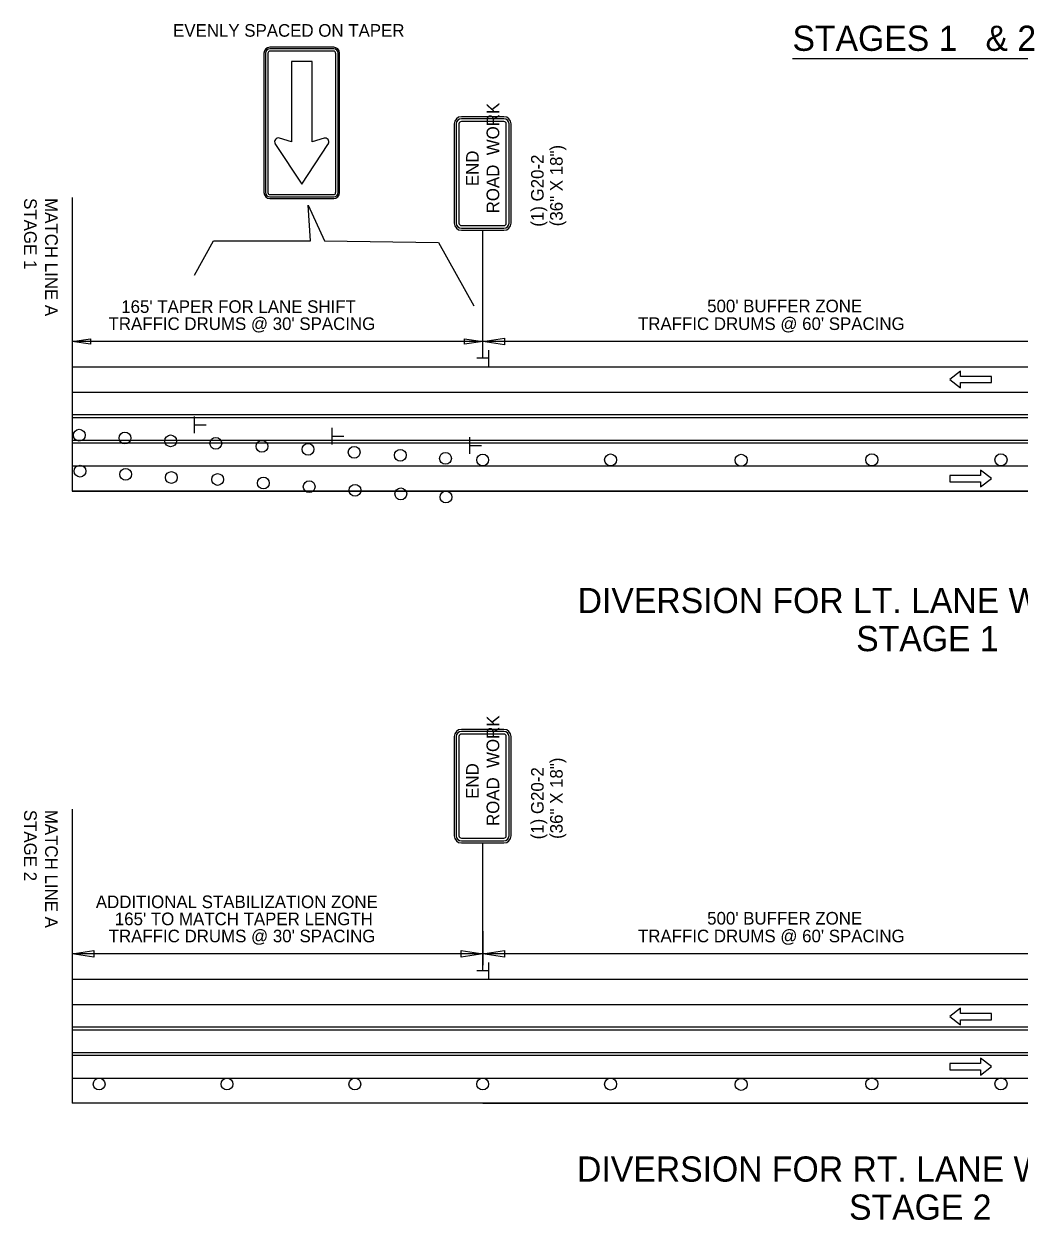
# Model space of a CAD drawing. Extents: x 1930579 to 1937984, y 596452 to 597630.
# Drawn here: x 1936470 to 1936944, y 596628 to 597198 of the extents above; entities that cross this region are included whole.
import ezdxf

# ---------------------------------------------------------------- set-up
doc = ezdxf.new("R2010")
doc.units = 0
for name, color, linetype in [('Default', 7, 'Continuous'), ('P_TC_Signs_Permanent', 7, 'Continuous'), ('P_TC_Signs_Temporary', 7, 'Continuous'), ('R_Annotation', 7, 'Continuous'), ('R_Striping', 7, 'Continuous')]:
    doc.layers.add(name, color=color, linetype=linetype)

msp = doc.modelspace()

# ---------------------------------------------------------------- linework, layer by layer
at = {"layer": 'Default'}
for p, q in [((1936835.84, 597181.22), (1936964.15, 597181.22)), ((1936493.11, 597114.97), (1936493.11, 596975.31)), ((1936493.11, 597046.45), (1936501.81, 597047.75)), ((1936688.44, 597046.45), (1936493.11, 597046.45)), ((1936501.81, 597045.15), (1936493.11, 597046.45)), ((1936501.81, 597047.75), (1936501.81, 597045.15)), ((1936679.75, 597045.15), (1936679.75, 597047.75)), ((1936679.75, 597047.75), (1936688.44, 597046.45)), ((1936688.44, 597046.45), (1936679.75, 597045.15)), ((1936997.05, 597046.45), (1936688.44, 597046.45)), ((1936688.53, 597046.45), (1936698.83, 597048)), ((1936698.83, 597044.9), (1936688.53, 597046.45)), ((1936698.83, 597048), (1936698.83, 597044.9)), ((1936691.23, 597042.43), (1936691.23, 597034.45)), ((1937498.74, 597034.31), (1936493.11, 597034.31)), ((1936691.12, 597038.47), (1936685.67, 597038.47)), ((1936493.11, 597022.31), (1937498.74, 597022.31)), ((1937498.74, 597011.52), (1936493.11, 597011.52)), ((1937498.74, 597010.14), (1936493.11, 597010.14)), ((1936551.31, 597002.87), (1936551.31, 597010.85)), ((1936551.43, 597006.84), (1936556.87, 597006.84)), ((1936616.72, 596997.46), (1936616.72, 597005.44)), ((1936616.84, 597001.42), (1936622.29, 597001.42)), ((1936682.29, 596992.94), (1936682.29, 597000.92)), ((1937498.74, 596999.41), (1936493.11, 596999.41)), ((1937498.74, 596998.03), (1936493.11, 596998.03)), ((1936682.4, 596996.91), (1936687.85, 596996.91)), ((1936493.11, 596987.31), (1937498.74, 596987.31)), ((1936493.11, 596975.31), (1936773.63, 596975.31)), ((1937498.74, 596975.31), (1936493.11, 596975.31)), ((1936757.75, 596975.31), (1937032.82, 596975.31)), ((1936493.11, 596823.85), (1936493.11, 596683.94)), ((1936688.44, 596765.87), (1936688.44, 596749.76)), ((1936493.11, 596755.08), (1936503.42, 596756.63)), ((1936503.42, 596756.63), (1936503.42, 596753.53)), ((1936678.23, 596753.53), (1936678.23, 596756.63)), ((1936678.23, 596756.63), (1936688.53, 596755.08)), ((1936688.53, 596755.08), (1936698.83, 596756.63)), ((1936698.83, 596756.63), (1936698.83, 596753.53)), ((1936688.53, 596755.08), (1936493.11, 596755.08)), ((1936503.42, 596753.53), (1936493.11, 596755.08)), ((1936688.53, 596755.08), (1936678.23, 596753.53)), ((1936997.05, 596755.08), (1936688.44, 596755.08)), ((1936698.83, 596753.53), (1936688.53, 596755.08)), ((1936691.23, 596750.89), (1936691.23, 596742.91)), ((1936691.12, 596746.92), (1936685.67, 596746.92)), ((1937498.74, 596742.94), (1936493.11, 596742.94)), ((1936493.11, 596730.94), (1937498.74, 596730.94)), ((1937498.74, 596720.15), (1936493.11, 596720.15)), ((1937498.74, 596718.77), (1936493.11, 596718.77)), ((1937498.74, 596708.04), (1936493.11, 596708.04)), ((1937498.74, 596706.66), (1936493.11, 596706.66)), ((1936493.11, 596695.94), (1937498.74, 596695.94)), ((1937498.74, 596683.94), (1936493.11, 596683.94)), ((1936688.44, 596683.94), (1936773.63, 596683.94)), ((1936757.75, 596683.94), (1937032.82, 596683.94))]:
    msp.add_line(p, q, dxfattribs=at)
for centre, radius in [((1936496.43, 597001.89), 2.81), ((1936518.18, 597000.54), 2.81), ((1936539.92, 596999.19), 2.81), ((1936561.41, 596998), 2.81), ((1936583.36, 596996.58), 2.81), ((1936605.32, 596995.17), 2.81), ((1936627.27, 596993.75), 2.81), ((1936649.22, 596992.34), 2.81), ((1936670.72, 596990.86), 2.81), ((1936688.44, 596990.1), 2.81), ((1936749.3, 596990.1), 2.87), ((1936811.44, 596989.95), 2.87), ((1936873.58, 596990.16), 2.87), ((1936935.06, 596990.17), 2.87), ((1936496.8, 596984.78), 2.81), ((1936518.53, 596983.27), 2.81), ((1936540.25, 596981.76), 2.81), ((1936562.28, 596980.82), 2.81), ((1936584.07, 596979.1), 2.81), ((1936605.86, 596977.39), 2.81), ((1936627.65, 596975.67), 2.81), ((1936649.45, 596973.95), 2.81), ((1936670.92, 596972.45), 2.81), ((1936505.88, 596693.1), 2.81), ((1936566.73, 596693.1), 2.81), ((1936627.59, 596693.1), 2.81), ((1936688.44, 596693.1), 2.81), ((1936749.3, 596693.1), 2.87), ((1936811.44, 596692.96), 2.87), ((1936873.58, 596693.16), 2.87), ((1936935.06, 596693.18), 2.87)]:
    msp.add_circle(centre, radius, dxfattribs=at)
at = {"layer": 'P_TC_Signs_Permanent'}
for p, q in [((1936584.33, 597183.71), (1936584.33, 597117.33)), ((1936585.08, 597183.71), (1936585.08, 597117.33)), ((1936586.2, 597183.71), (1936586.2, 597117.33)), ((1936617.51, 597186.52), (1936587.14, 597186.52)), ((1936617.51, 597185.77), (1936587.14, 597185.77)), ((1936617.51, 597184.65), (1936587.14, 597184.65)), ((1936618.45, 597117.33), (1936618.45, 597183.71)), ((1936619.58, 597117.33), (1936619.58, 597183.71)), ((1936620.33, 597117.33), (1936620.33, 597183.71)), ((1936587.14, 597116.4), (1936617.51, 597116.4)), ((1936587.14, 597115.27), (1936617.51, 597115.27)), ((1936587.14, 597114.52), (1936617.51, 597114.52))]:
    msp.add_line(p, q, dxfattribs=at)
for points in [[(1936612.96, 597143.22), (1936607.2, 597141.5), (1936607.2, 597179.77), (1936597.45, 597179.77), (1936597.45, 597141.5), (1936591.7, 597143.26)], [(1936589.88, 597140.26), (1936602.33, 597121.27), (1936614.73, 597140.27)]]:
    msp.add_lwpolyline(points, dxfattribs=at)
for centre, radius, start, end in [((1936587.14, 597183.71), 2.81, 90, 180), ((1936587.14, 597183.71), 2.06, 90, 180), ((1936587.14, 597183.71), 0.938, 90, 180), ((1936617.51, 597183.71), 2.81, 360, 90), ((1936617.51, 597183.71), 2.06, 360, 90), ((1936617.51, 597183.71), 0.937, 360, 90), ((1936591.21, 597141.53), 1.8, 74.0309, 213.4755), ((1936613.44, 597141.53), 1.76, 326.5994, 105.9691), ((1936527.15, 597099.16), 75, 33.2286, 33.4755), ((1936677.53, 597099.27), 75, 146.5994, 146.857), ((1936587.14, 597117.33), 2.81, 180, 270), ((1936587.14, 597117.33), 2.06, 180, 270), ((1936587.14, 597117.33), 0.938, 180, 270), ((1936617.51, 597117.33), 2.81, 270, 360), ((1936617.51, 597117.33), 2.06, 270, 360), ((1936617.51, 597117.33), 0.938, 270, 360)]:
    msp.add_arc(centre, radius, start, end, dxfattribs=at)
at = {"layer": 'P_TC_Signs_Temporary'}
for p, q in [((1936674.89, 597150.04), (1936674.89, 597102.79)), ((1936675.83, 597150.04), (1936675.83, 597102.79)), ((1936677.14, 597150.04), (1936677.14, 597102.79)), ((1936698.52, 597153.42), (1936678.27, 597153.42)), ((1936698.52, 597152.48), (1936678.27, 597152.48)), ((1936698.52, 597151.17), (1936678.27, 597151.17)), ((1936699.64, 597102.79), (1936699.64, 597150.04)), ((1936700.96, 597102.79), (1936700.96, 597150.04)), ((1936701.89, 597102.79), (1936701.89, 597150.04)), ((1936678.27, 597101.67), (1936698.52, 597101.67)), ((1936678.27, 597100.36), (1936698.52, 597100.36)), ((1936678.27, 597099.42), (1936698.52, 597099.42)), ((1936674.89, 596858.5), (1936674.89, 596811.25)), ((1936675.83, 596858.5), (1936675.83, 596811.25)), ((1936677.14, 596858.5), (1936677.14, 596811.25)), ((1936698.52, 596861.87), (1936678.27, 596861.87)), ((1936698.52, 596860.93), (1936678.27, 596860.93)), ((1936698.52, 596859.62), (1936678.27, 596859.62)), ((1936699.64, 596811.25), (1936699.64, 596858.5)), ((1936700.96, 596811.25), (1936700.96, 596858.5)), ((1936701.89, 596811.25), (1936701.89, 596858.5)), ((1936678.27, 596810.12), (1936698.52, 596810.12)), ((1936678.27, 596808.81), (1936698.52, 596808.81)), ((1936678.27, 596807.87), (1936698.52, 596807.87))]:
    msp.add_line(p, q, dxfattribs=at)
for centre, radius, start, end in [((1936678.27, 597150.04), 3.38, 90, 180), ((1936678.27, 597150.04), 2.44, 90, 180), ((1936678.27, 597150.04), 1.13, 90, 180), ((1936698.52, 597150.04), 3.38, 360, 90), ((1936698.52, 597150.04), 2.44, 360, 90), ((1936698.52, 597150.04), 1.13, 360, 90), ((1936678.27, 597102.79), 3.38, 180, 270), ((1936678.27, 597102.79), 2.44, 180, 270), ((1936678.27, 597102.79), 1.13, 180, 270), ((1936698.52, 597102.79), 2.44, 270, 360), ((1936698.52, 597102.79), 1.13, 270, 360), ((1936698.52, 597102.79), 3.38, 270, 360), ((1936678.27, 596858.5), 3.38, 90, 180), ((1936678.27, 596858.5), 2.44, 90, 180), ((1936678.27, 596858.5), 1.13, 90, 180), ((1936698.52, 596858.5), 3.38, 360, 90), ((1936698.52, 596858.5), 2.44, 360, 90), ((1936698.52, 596858.5), 1.13, 360, 90), ((1936678.27, 596811.25), 3.38, 180, 270), ((1936678.27, 596811.25), 2.44, 180, 270), ((1936678.27, 596811.25), 1.13, 180, 270), ((1936698.52, 596811.25), 2.44, 270, 360), ((1936698.52, 596811.25), 1.13, 270, 360), ((1936698.52, 596811.25), 3.38, 270, 360)]:
    msp.add_arc(centre, radius, start, end, dxfattribs=at)
at = {"layer": 'R_Annotation'}
for p, q in [((1936688.39, 597099.42), (1936688.39, 597038.47)), ((1936688.39, 596807.87), (1936688.39, 596746.92))]:
    msp.add_line(p, q, dxfattribs=at)
msp.add_lwpolyline([(1936551.31, 597078.12), (1936560.31, 597094.42), (1936606.55, 597094.42), (1936605.35, 597111.31), (1936613.15, 597094.42), (1936667.35, 597093.63), (1936684.23, 597063.48)], dxfattribs=at)
at = {"layer": 'R_Striping'}
for points in [[(1936915.85, 597032.39), (1936910.66, 597028.39), (1936915.85, 597024.39), (1936915.85, 597026.89), (1936930.56, 597026.89), (1936930.56, 597029.89), (1936915.85, 597029.89)], [(1936925.37, 596977.26), (1936930.56, 596981.26), (1936925.37, 596985.26), (1936925.37, 596982.76), (1936910.66, 596982.76), (1936910.66, 596979.76), (1936925.37, 596979.76)], [(1936915.85, 596729.24), (1936910.66, 596725.24), (1936915.85, 596721.24), (1936915.85, 596723.74), (1936930.56, 596723.74), (1936930.56, 596726.74), (1936915.85, 596726.74)], [(1936925.37, 596697.41), (1936930.56, 596701.41), (1936925.37, 596705.41), (1936925.37, 596702.91), (1936910.66, 596702.91), (1936910.66, 596699.91), (1936925.37, 596699.91)]]:
    msp.add_lwpolyline(points, close=True, dxfattribs=at)

# ---------------------------------------------------------------- texts
at = {"layer": 'Default'}
for s, height, rotation, p in [('STAGES 1   & 2', 12, 360, (1936835.84, 597184.79)), ('STAGE 1', 6, 270, (1936470.18, 597114.71)), ('MATCH LINE A ', 6, 270, (1936480.18, 597114.71)), ("165' TAPER FOR LANE SHIFT", 6, 360, (1936516.4, 597060.08)), ("500' BUFFER ZONE", 6, 360, (1936795.24, 597060.38)), ("TRAFFIC DRUMS @ 30' SPACING", 6, 360, (1936510.37, 597051.95)), ("TRAFFIC DRUMS @ 60' SPACING", 6, 360, (1936762.31, 597051.95)), ('DIVERSION FOR LT. LANE WORK ZONE', 12, 360, (1936733.6, 596917.22)), ('STAGE 1', 12, 360, (1936866.17, 596899.1)), ('STAGE 2', 6, 270, (1936470.18, 596823.6)), ('MATCH LINE A ', 6, 270, (1936480.18, 596823.6)), ('ADDITIONAL STABILIZATION ZONE', 6, 360, (1936504.32, 596776.83)), ("165' TO MATCH TAPER LENGTH", 6, 360, (1936513.36, 596768.71)), ("500' BUFFER ZONE", 6, 360, (1936795.24, 596769.01)), ("TRAFFIC DRUMS @ 30' SPACING", 6, 360, (1936510.44, 596760.58)), ("TRAFFIC DRUMS @ 60' SPACING", 6, 360, (1936762.31, 596760.58)), ('DIVERSION FOR RT. LANE WORK ZONE', 12, 360, (1936733.32, 596646.67)), ('STAGE 2', 12, 360, (1936862.77, 596628.55))]:
    msp.add_text(s, height=height, rotation=rotation, dxfattribs=at).set_placement(p)
at = {"layer": 'P_TC_Signs_Temporary'}
for s, p in [('ROAD  WORK', (1936696.27, 597107.46)), ('END', (1936686.52, 597120.39)), ('ROAD  WORK', (1936696.27, 596815.91)), ('END', (1936686.52, 596828.84))]:
    msp.add_text(s, height=6, rotation=90, dxfattribs=at).set_placement(p)
at = {"layer": 'R_Annotation'}
for s, rotation, p in [('EVENLY SPACED ON TAPER', 0.0075, (1936541.07, 597191.5)), ('(36" X 18")', 90, (1936726.48, 597101.31)), ('(1) G20-2', 90, (1936717.43, 597101.1)), ('(36" X 18")', 90, (1936726.48, 596809.77)), ('(1) G20-2', 90, (1936717.43, 596809.55))]:
    msp.add_text(s, height=6, rotation=rotation, dxfattribs=at).set_placement(p)

doc.saveas('drawing.dxf')
